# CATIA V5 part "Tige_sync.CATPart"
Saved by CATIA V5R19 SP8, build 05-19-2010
Part number: Tige_sync
Bounding box of the stored display mesh (mm): x -24.804 to 362.804, y -9.831 to 9.831, z -7 to 7
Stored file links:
  G:\EU_thinkMotion\CFAO_2010\MMS_groupe1\MMS_groupe1\OK\vduret\vduret\CATIA\Tige_sync.CATPart
  G:\EU_thinkMotion\CFAO_2010\MMS_groupe1\MMS_groupe1\OK\vduret\vduret\CATIA\Profile_bati.CATPart
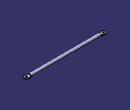
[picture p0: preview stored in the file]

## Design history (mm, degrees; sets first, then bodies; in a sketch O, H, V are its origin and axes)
Parameters
  Longueur_tige = 338 mm {= External.Largeur_bati -162mm}
  Diam_tige = 14 mm
External parameters (linked from other documents)
  External.Largeur_bati = 500 mm
Body1 (main body)
  Sketch1 on yz-plane, origin (0, 0, 0), H (0, 1, 0), V (0, 0, 1)
    circle A1 centre (0, 0) radius 7
    radius A1 = 7 {= Diam_tige /2}
  Pad1: profile Sketch1, direction (1, 0, 0), length 338 {= Longueur_tige}
  Sketch2 on xy-plane, origin (0, 0, 0), H (1, 0, 0), V (0, 1, 0)
    arc A1 centre (-15, 0) radius 10 from (-12.8955, 9.776) to (-12.8955, -9.776) ccw
    point P1 (-15, 0)
    circle A2 centre (-15, 0) radius 4
    reference projected line E1 (0, 7) -> (0, -7) from edge [start face of Pad1 | face of Pad1 from Sketch1.A1]
    circle A3 centre (353, 0) radius 4
    point P2 (353, 0)
    arc A4 centre (353, 0) radius 10 from (350.8955, -9.776) to (350.8955, 9.776) ccw
    reference projected line E2 (338, 7) -> (338, -7) from edge [face of Pad1 from Sketch1.A1 | end face of Pad1]
    line L1 (0, 7) -> (-12.8955, 9.776)
    point P3 (0, 7)
    line L2 (0, -7) -> (-12.8955, -9.776)
    point P4 (0, -7)
    reference projected line E3 (0, 7) -> (0, -7) from edge [start face of Pad1 | face of Pad1 from Sketch1.A1]
    reference projected line E4 (0, 7) -> (0, -7) from edge [start face of Pad1 | face of Pad1 from Sketch1.A1]
    line L3 (338, 7) -> (350.8955, 9.776)
    point P5 (338, 7)
    line L4 (338, -7) -> (350.8955, -9.776)
    point P6 (338, -7)
    reference projected line E5 (338, 7) -> (338, -7) from edge [face of Pad1 from Sketch1.A1 | end face of Pad1]
    reference projected line E6 (338, 7) -> (338, -7) from edge [face of Pad1 from Sketch1.A1 | end face of Pad1]
    line L5 (0, 7) -> (0, -7)
    line L6 (338, 7) -> (338, -7)
    radius A2 = 4
    radius A1 = 10
    distance P1 E1 = 15
    radius A4 = 10
    radius A3 = 4
    distance E2 P2 = 15
    distance H P4 = 7 {= Diam_tige /2}
    distance P3 H = 7 {= Diam_tige /2}
    distance P6 H = 7 {= Diam_tige /2}
    distance P5 H = 7 {= Diam_tige /2}
    coincidence: P1 H, P2 H, P4 E3, P3 E4, P6 E5, P5 E6
    tangency: L2 A1, L1 A1, L4 A4, L3 A4
    vertical: L5 V, L6 V
  Pad2: profile Sketch2, direction (0, 0, -1), length 2, mirrored extent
